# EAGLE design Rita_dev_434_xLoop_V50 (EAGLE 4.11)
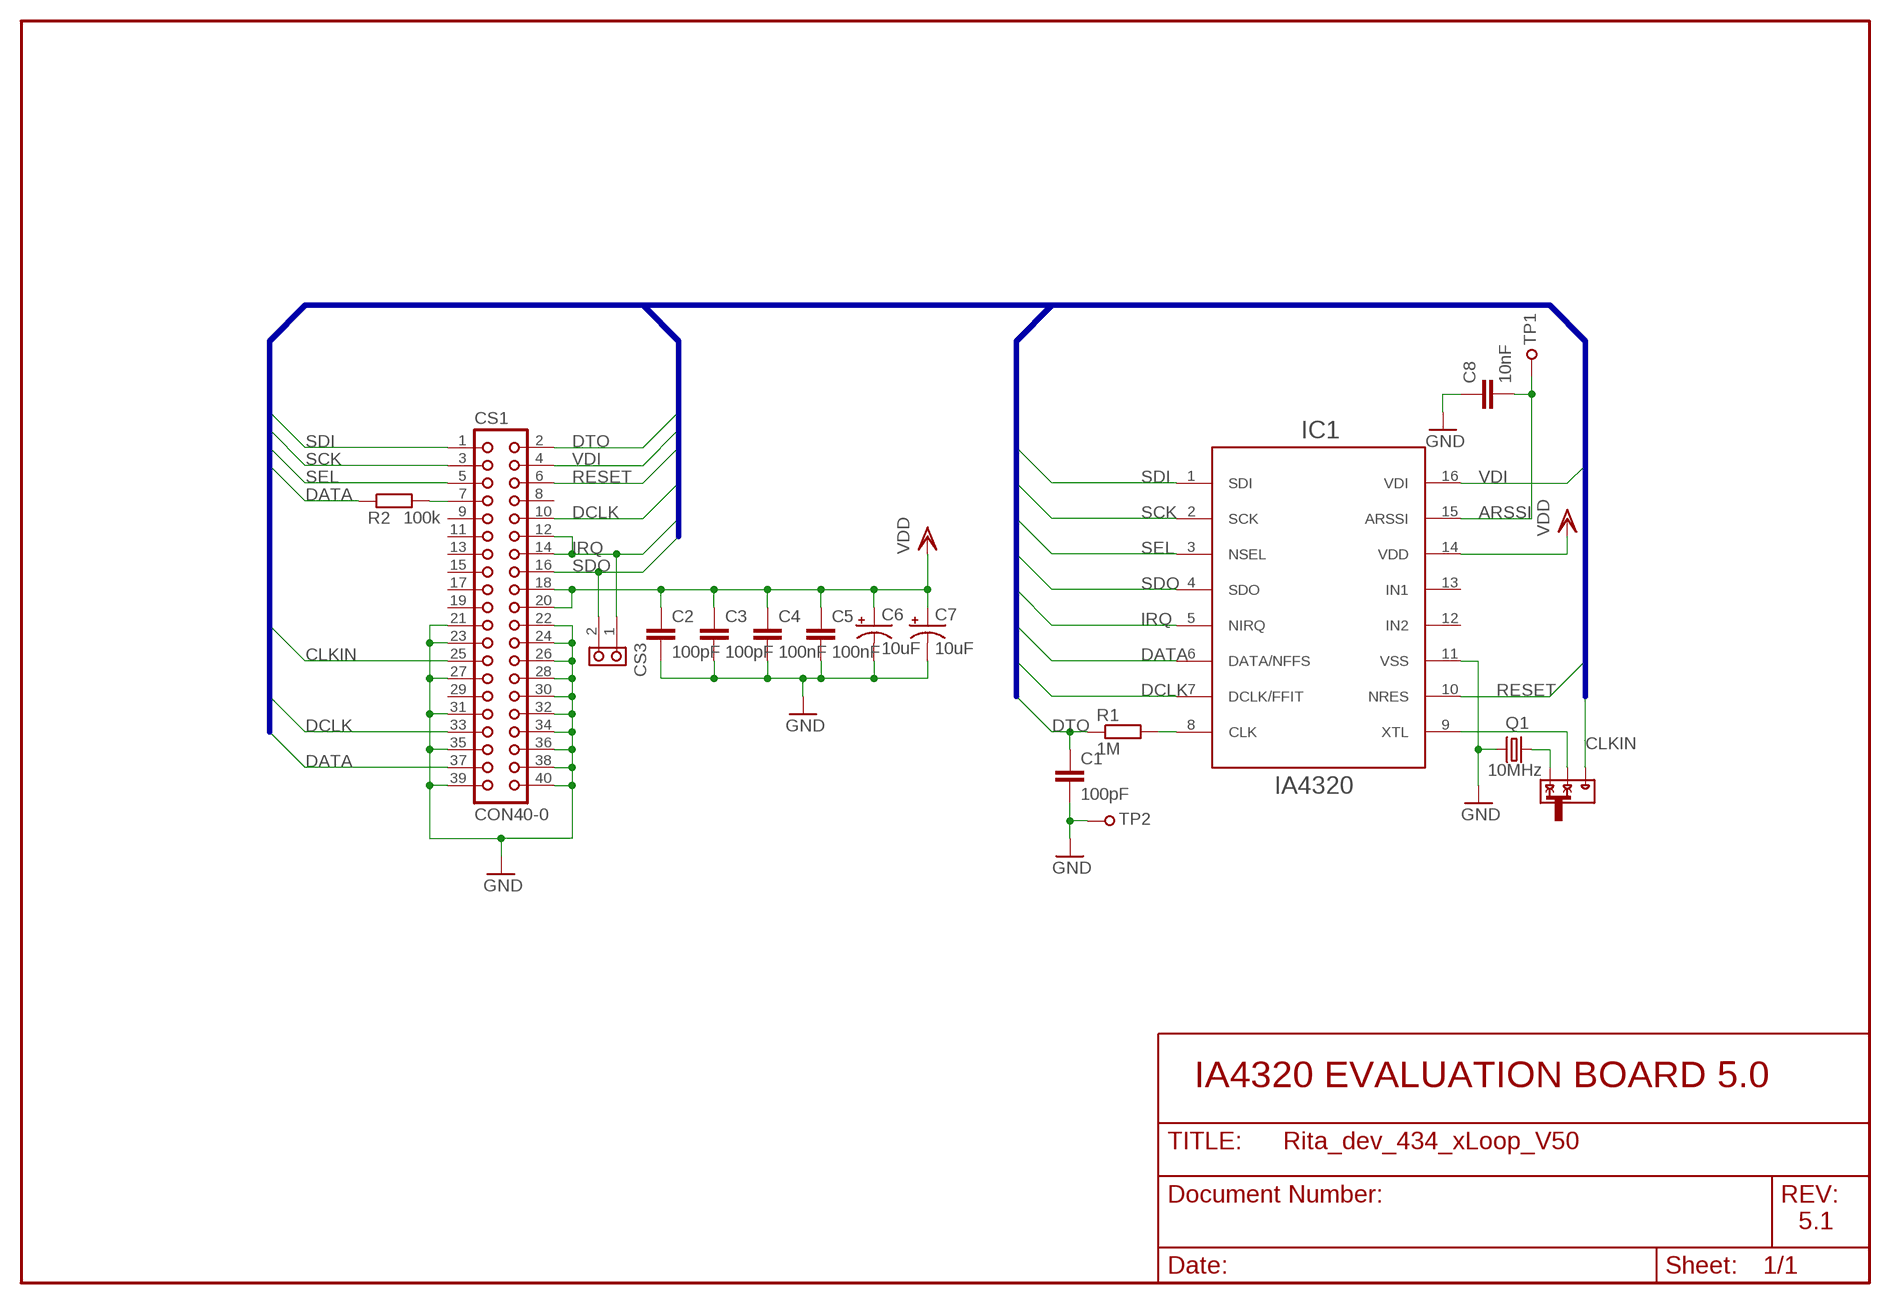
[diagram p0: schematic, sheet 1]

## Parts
C1  100pF  C-EUC0603  [C0603]
C2  100pF  C-EUC0603  [C0603]
C3  100pF  C-EUC0603  [C0603]
C4  100nF  C-EUC0603  [C0603]
C5  100nF  C-EUC0603  [C0603]
C6  10uF  CPOL-USA/3216-18R  [A/3216-18R]
C7  10uF  CPOL-USA/3216-18R  [A/3216-18R]
C8  10nF  C-EUC0603  [C0603]
CS1  CON40-0  [PANDUIT-057-040-0-INTEGRATION]
CS3  CRS-2  [CRS-2]
IC1  IA4320  RITATSSOP  [TSSOP-16]
Q1  10MHz  CRYTALSM49  [SM49]
R1  1M  R-EU_R0603  [R0603]
R2  100k  R-EU_R0603  [R0603]
SW1  SWITCH-RETRET  [SWITCH]
TP1  TESTPOINT  TESTPOINT39MIL  [TESTPOINT1,0]
TP2  TESTPOINT39MIL  [TESTPOINT1,0]

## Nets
ARSSI: C8.2 IC1.15(ARSSI) TP1.1
CLKIN: CS1.25 SW1.1
DATA: CS1.37 IC1.6(DATA/NFFS) R2.1
DCLK: CS1.10 CS1.33 IC1.7(DCLK/FFIT)
DTO: C1.1 CS1.2 R1.1
GND: C1.2 C2.2 C3.2 C4.2 C5.2 C6.- C7.- C8.1 CS1.21 CS1.22 CS1.23 CS1.24 CS1.26 CS1.27 CS1.28 CS1.30 CS1.31 CS1.32 CS1.34 CS1.35 CS1.36 CS1.38 CS1.39 CS1.40 IC1.11(VSS) Q1.2 TP2.1
IRQ: CS1.12 CS1.14 CS3.1(A) IC1.5(NIRQ)
N$1: CS1.7 R2.2
N$3: IC1.8(CLK) R1.2
N$4: IC1.9(XTL) SW1.2
N$6: Q1.1 SW1.3
RESET: CS1.6 IC1.10(NRES)
SCK: CS1.3 IC1.2(SCK)
SDI: CS1.1 IC1.1(SDI)
SDO: CS1.16 CS3.2(B) IC1.4(SDO)
SEL: CS1.5 IC1.3(NSEL)
VDD: C2.1 C3.1 C4.1 C5.1 C6.+ C7.+ CS1.18 CS1.20 IC1.14(VDD)
VDI: CS1.4 IC1.16(VDI)
Unconnected: CS1.8 CS1.9 CS1.11 CS1.13 CS1.15 CS1.17 CS1.19 CS1.29 IC1.12(IN2) IC1.13(IN1)

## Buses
B$1

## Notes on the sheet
- IA4320 EVALUATION BOARD 5.0
- 5.1

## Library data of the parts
C1-C5 C8 = rcl:C-EU: CAPACITOR, European symbol
C6 C7 = rcl:CPOL-US: POLARIZED CAPACITOR, American symbol
CS1 = lve:CON40
CS3 = lve:CRS-2: 2.54mm-es tuskesor krimpelheto csatlakozohoz
IC1 = lve:RITA: RITA
Q1 = crystal:CRYTAL: CRYSTAL
R1 R2 = rcl:R-EU_: RESISTOR, European symbol
SW1 = jumper:SWITCH-RET
TP1 TP2 = lve:TESTPOINT

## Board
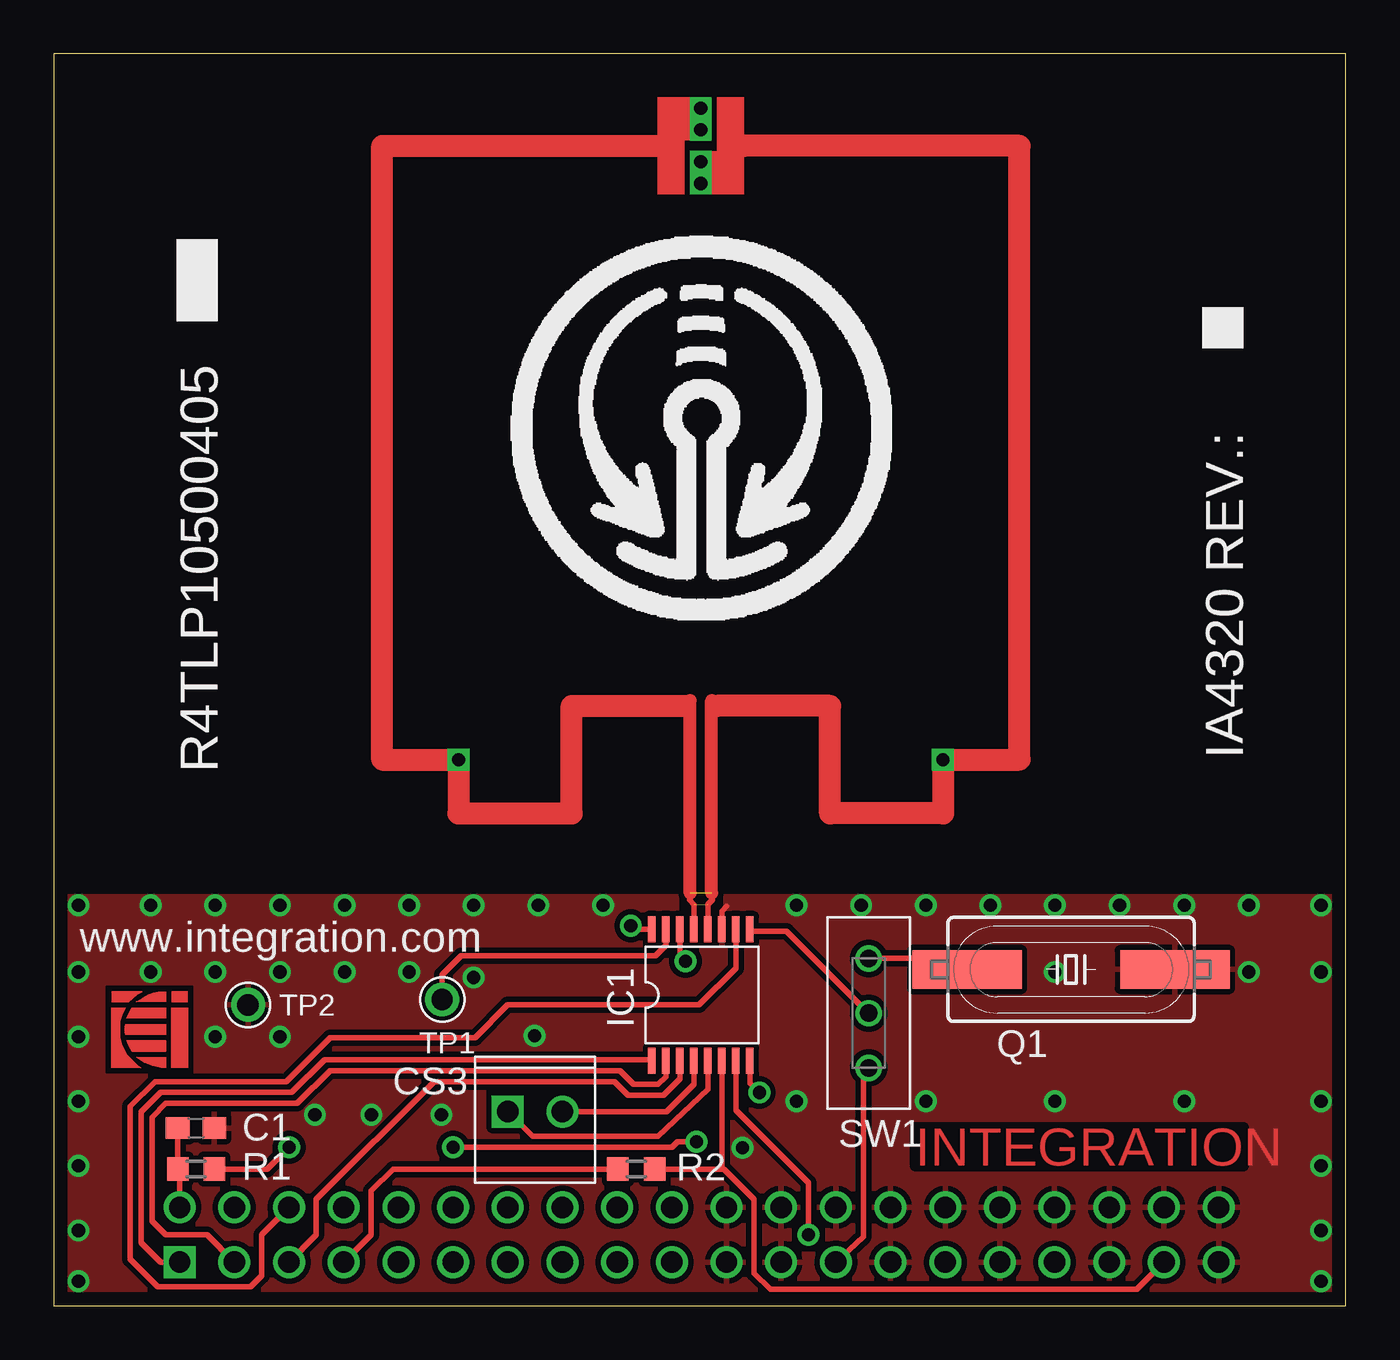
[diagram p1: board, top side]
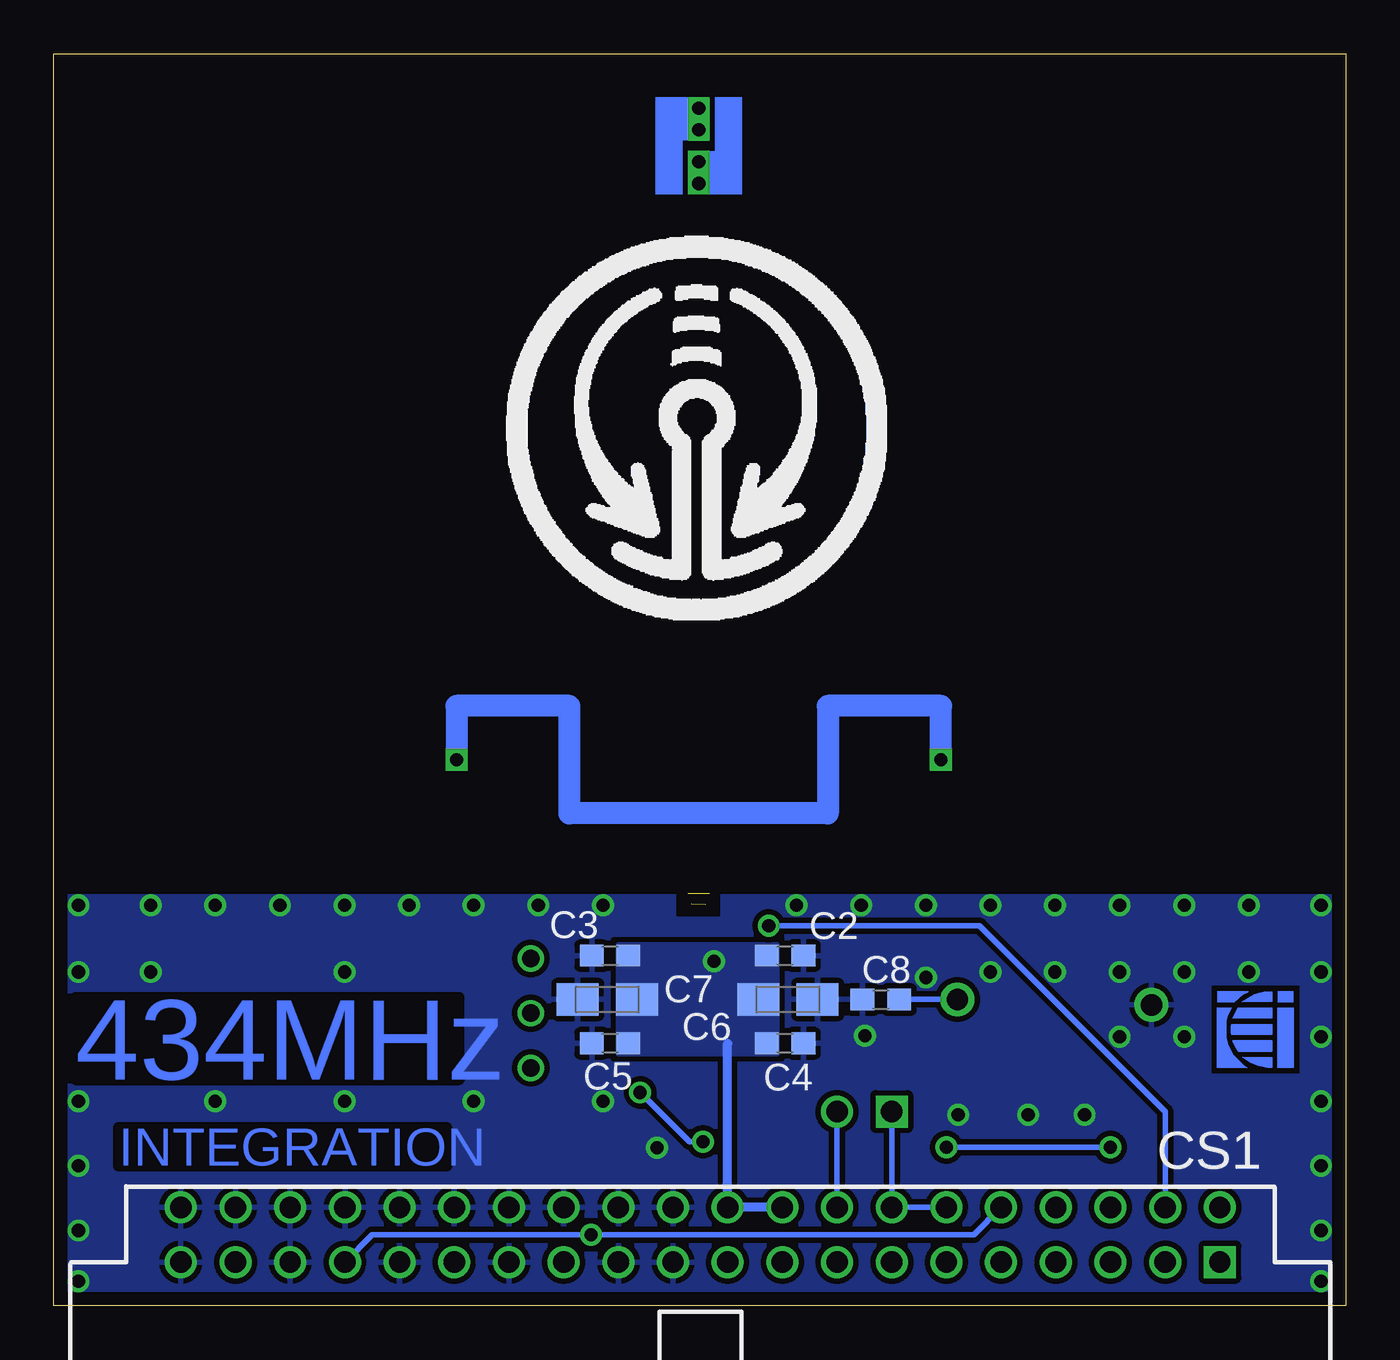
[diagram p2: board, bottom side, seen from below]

Size 60 x 58.13 mm. Coordinates in mm from the lower left corner, seen from the top.
Outline: 0,0 60,0 60,58.13 0,58.13 0,0
Copper layers (1*16): Top 0.035mm / dielectric 1.5mm / Bottom 0.035mm
Design rules "default_INTEGRATION": minimum track width 10mil, minimum drill 24mil, track to track 10mil, track to pad 10mil, pad to pad 10mil, via to via 10mil, smd to smd 10mil, copper to edge 25mil, drill to drill 8mil, minimum pad ring 8mil, minimum via ring 8mil, stop-mask expansion 4mil, vias tented up to drill 24mil, thermal gap 10mil
tRestrict: area 29.1,18.1 to 31.1,19; area 30.7,17.1 to 30.9,17.8; area 31.2,17.1 to 31.4,17.8; 1 lines
bRestrict: area 29.1,18.1 to 31.1,19; 5 lines

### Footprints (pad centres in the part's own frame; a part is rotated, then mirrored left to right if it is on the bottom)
C0603 = smd 1.1 x 1: 1 -0.85,0; 2 0.85,0
A/3216-18R = smd 1.95 x 1.5: + 1.375,0; - -1.375,0
PANDUIT-057-040-0-INTEGRATION = drill 0.991 square: 1 -24.13,-1.27 | drill 0.991 round: 2 -24.13,-3.81; 3 -21.59,-1.27; 4 -21.59,-3.81; 5 -19.05,-1.27; 6 -19.05,-3.81; 7 -16.51,-1.27; 8 -16.51,-3.81; 9 -13.97,-1.27; 10 -13.97,-3.81; 11 -11.43,-1.27; 12 -11.43,-3.81; 13 -8.89,-1.27; 14 -8.89,-3.81; 15 -6.35,-1.27; 16 -6.35,-3.81; 17 -3.81,-1.27; 18 -3.81,-3.81; 19 -1.27,-1.27; 20 -1.27,-3.81; 21 1.27,-1.27; 22 1.27,-3.81; 23 3.81,-1.27; 24 3.81,-3.81; 25 6.35,-1.27; 26 6.35,-3.81; 27 8.89,-1.27; 28 8.89,-3.81; 29 11.43,-1.27; 30 11.43,-3.81; 31 13.97,-1.27; 32 13.97,-3.81; 33 16.51,-1.27; 34 16.51,-3.81; 35 19.05,-1.27; 36 19.05,-3.81; 37 21.59,-1.27; 38 21.59,-3.81; 39 24.13,-1.27; 40 24.13,-3.81
CRS-2 = drill 0.991 square: 1 -1.27,0 | drill 0.991 round: 2 1.27,0
TSSOP-16 = smd 1.2 x 0.35: 1 -3.107,2.223; 2 -3.107,1.573; 3 -3.107,0.922; 4 -3.107,0.273; 5 -3.107,-0.378; 6 -3.107,-1.028; 7 -3.107,-1.677; 8 -3.107,-2.328; 9 2.993,-2.328; 10 2.993,-1.677; 11 2.993,-1.028; 12 2.993,-0.378; 13 2.993,0.273; 14 2.993,0.922; 15 2.993,1.573; 16 2.993,2.223
SM49 = smd 5.08 x 1.778: 1 -4.826,0; 2 4.826,0
R0603 = smd 1 x 1.1: 1 -0.85,0; 2 0.85,0
SWITCH = drill 0.813 round: 1 -2.54,0; 2 0,0; 3 2.54,0
TESTPOINT1,0 = drill 0.991 pad 1.575 round: 1 0,0

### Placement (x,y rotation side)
C1  6.6,8.26 0 top
C2  26.04,16.26 0 bottom
C3  34.16,16.26 180 bottom
C4  26.04,12.19 0 bottom
C5  34.16,12.19 180 bottom
C6  25.91,14.22 180 bottom
C7  34.29,14.22 0 bottom
C8  21.59,14.22 0 bottom
CS1  29.97,0.76 180 bottom
CS3  22.35,9.02 0 top
IC1  30,14.49 90 top
Q1  47.24,15.62 0 top
R1  6.6,6.35 0 top
R2  27.05,6.35 180 top
SW1  37.85,13.59 90 top
TP1  18.03,14.22 0 top
TP2  9.02,13.97 0 top
U$1  [RECEIVE-ICON]  30.12,41.15 0 bottom
U$2  [LOGO-SMALL]  4.45,12.83 0 top
U$3  [RECEIVE-ICON]  30.1,41.15 0 top
U$4  [LOGO-SMALL]  4.19,12.83 0 bottom

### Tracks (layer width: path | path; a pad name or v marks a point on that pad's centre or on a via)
ANT2  (1 unrouted)
  Top 0.254: 29.73,17.48 29.73,18.63 29.52,18.85 | 30.38,17.48 30.38,18.65 30.58,18.85
ARSSI
  Top 0.254: IC1.15 28.43,16.74 27.94,16.26 18.92,16.26 18.03,15.37 TP1.1
  Bottom 0.254: TP1.1 C8.2
CLKIN
  Top 0.254: SW1.1 37.59,10.8 37.59,3.2 CS1.25
DATA
  Top 0.254: R2.1 27.9,6.4 | R2.1 31.03,6.35 | R2.1 27.9,6.3 | 31.03,6.35 IC1.6 | 31.03,6.35 31.11,6.35 32.51,4.95 32.51,1.52 33.27,0.76 50.29,0.76 CS1.37
DCLK  (via drill 0.61 pad 1.02)
  Top 0.254: v35.05,3.3 35.05,5.71 31.68,9.09 IC1.7
  Bottom 0.254: CS1.10 17.27,3.3 v35.05,3.3 45.21,3.3 CS1.33
DTO
  Top 0.254: C1.1 5.75,6.39 5.71,6.35 | 5.71,6.35 R1.1 | CS1.2 5.84,6.22 5.71,6.35
GND  (via drill 0.61 pad 1.02)
  Top 0.254: IC1.11 31.02,18.32 31.24,18.54
  other vias: 1.15,18.6 25.5,18.6 22.5,18.6 19.5,18.6 16.5,18.6 13.5,18.6 10.5,18.6 7.5,18.6 4.5,18.6 34.5,18.6 37.5,18.6 40.5,18.6 43.5,18.6 46.5,18.6 49.5,18.6 52.5,18.6 55.5,18.6 58.85,18.6 58.85,15.5 58.85,9.5 58.85,6.5 58.85,3.5 58.85,1.15 1.15,15.5 1.15,12.5 1.15,9.5 1.15,6.5 1.15,3.5 1.15,1.15 14.75,8.87 12.12,8.87 4.5,15.5 7.5,15.5 10.5,15.5 13.5,15.5 16.5,15.5 19.5,15.25 55.5,15.5 46.5,15.5 18,8.87 22.33,12.54 52.5,9.5 46.5,9.5 40.5,9.5 7.5,12.5 10.5,12.5 34.5,9.5 31.98,7.35
  pour Bottom (rank 2): 0,0 0,19 60,19 60,0
  pour Top (rank 2): 0,0 0,19 60,19 60,0
IRQ
  Top 0.254: IC1.5 30.38,10.06 28.07,7.87 22.23,7.87 CS3.1
  Bottom 0.254: CS3.1 CS1.14 CS1.12
N$1
  Top 0.254: R2.2 15.75,6.35 14.73,5.33 14.73,3.3 CS1.7
N$3  (via drill 0.61 pad 1.02)
  Top 0.254: R1.2 9.91,6.35 v10.92,7.37 | v18.54,7.37 28.7,7.37 28.96,7.62 v29.84,7.62 | IC1.8 32.33,10.35 v32.77,9.91
  Bottom 0.254: v10.92,7.37 v18.54,7.37 | v29.84,7.62 30.48,7.62 v32.77,9.91
N$4
  Top 0.254: IC1.9 32.38,17.43 32.38,17.4 34.04,17.4 SW1.2
N$6
  Top 0.254: 42.31,15.57 Q1.1 | 42.31,15.57 42.29,15.56 | 42.31,15.57 42.31,15.6 41.78,16.13 SW1.3
RESET
  Top 0.254: IC1.10 31.68,15.68 29.97,13.97 21.08,13.97 19.56,12.45 12.83,12.45 10.79,10.41 4.7,10.41 3.56,9.27 3.56,2.16 4.83,0.89 9.14,0.89 9.65,1.4 9.65,3.3 CS1.6
S$1  (1 unrouted)
  Top 0.61: 29.55,19.16 29.55,28.11 | 30.55,19.16 30.55,28.11
S$159  (via drill 0.61 pad 0.41)
  other vias: 30.05,53.11
S$160  (via drill 0.61 pad 0.41)
  other vias: 30.05,54.61
S$164  (via drill 0.61, 0.61 pad 0.41)
  Top 1.016: 28.05,53.86 15.25,53.86 15.25,25.36 v18.8,25.36 18.8,22.86 24.05,22.86 | 32.05,53.86 44.85,53.86 44.85,25.36 v41.3,25.36 41.3,22.86 36.05,22.86 36.05,27.86 30.8,27.86
  Bottom 1.016: v18.8,25.36 18.8,27.86 24.05,27.86 24.05,22.86 36.05,22.86 36.05,27.86 41.3,27.86 v41.3,25.36
S$165
  Top 1.016: 29.3,27.86 24.05,27.86 24.05,22.86
S$168  (via drill 0.61 pad 0.41)
  other vias: 30.05,52.11
S$169  (via drill 0.61 pad 0.41)
  other vias: 30.05,55.61
SCK
  Top 0.254: IC1.2 28.43,10.65 28.07,10.29 26.92,10.29 26.29,10.92 12.83,10.92 11.3,9.4 5.21,9.4 4.57,8.76 4.57,3.94 5.21,3.3 7.11,3.3 CS1.3
SDI
  Top 0.254: CS1.1 4.95,2.03 4.06,2.92 4.06,9.02 4.95,9.91 11.05,9.91 12.57,11.43 27.73,11.43 IC1.1
SDO
  Top 0.254: IC1.4 29.73,10.3 28.45,9.02 CS3.2
  Bottom 0.254: CS1.16 CS3.2
SEL
  Top 0.254: IC1.3 29.08,10.54 28.32,9.78 26.67,9.78 26.04,10.41 17.65,10.41 12.19,4.95 12.19,3.3 CS1.5
VDD  (via drill 0.61 pad 1.02)
  Top 0.254: IC1.14 29.08,16.26 v29.34,16
  Bottom 0.406: CS1.18 CS1.20 28.7,12.19
  pour Bottom (no thermals): 26.42,16.76 33.78,16.76 33.78,11.71 26.42,11.71
VDI  (via drill 0.61 pad 1.02)
  Top 0.254: IC1.16 26.97,17.48 v26.8,17.65
  Bottom 0.254: v26.8,17.65 17.02,17.65 8.38,9.02 CS1.4
(copper drawn outside any net)
  shapes: Bottom area x5, Top area x6

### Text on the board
Top: INTEGRATION
Bottom: 434MHz | INTEGRATION
tPlace: R4TLP10500405 | IA4320 REV.: | www.integration.com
